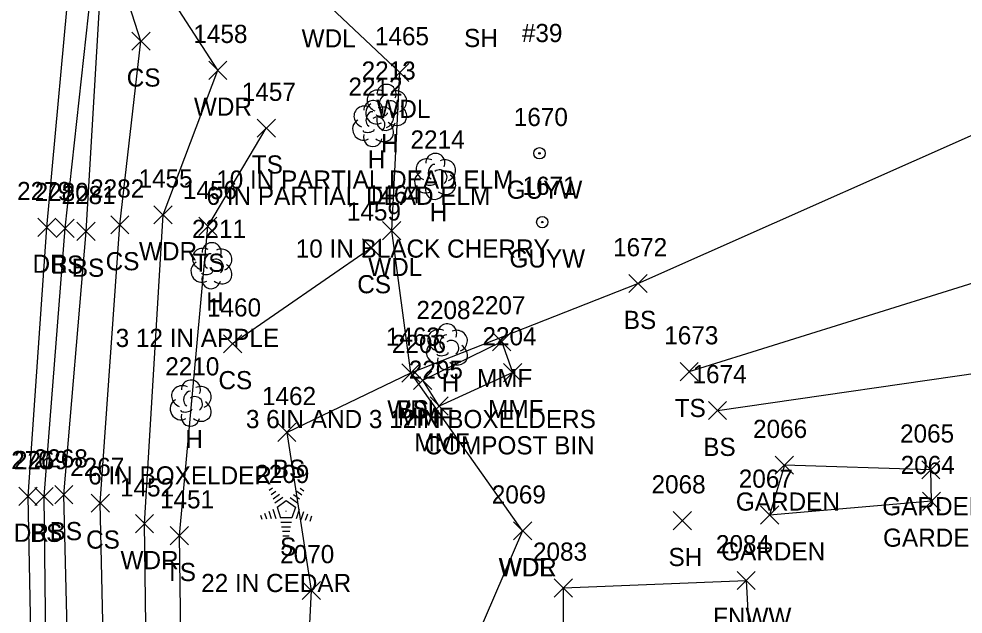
# Model space of a CAD drawing. Extents: x 1761340 to 1763889, y 696770 to 706023.
# Drawn here: x 1761657.7 to 1761761.6, y 700749.1 to 700814.6 of the extents above; entities that cross this region are included whole.
import ezdxf

# ---------------------------------------------------------------- set-up
doc = ezdxf.new("R2010")
doc.units = 0
for name, color, linetype in [('L_A', 7, 'Continuous'), ('L_C', 7, 'Continuous'), ('L_I', 7, 'Continuous'), ('L_TIC', 7, 'Continuous'), ('LAPB', 7, 'Continuous'), ('LAWA', 7, 'Continuous'), ('LDEFAULT', 7, 'Continuous'), ('LELB', 7, 'Continuous'), ('LFNC', 7, 'Continuous'), ('LTC', 7, 'Continuous'), ('LTD', 7, 'Continuous'), ('R_A', 7, 'Continuous'), ('R_I', 7, 'Continuous'), ('R_TIC', 7, 'Continuous'), ('RDP', 7, 'Continuous'), ('U_A', 7, 'Continuous'), ('U_C', 7, 'Continuous'), ('U_I', 7, 'Continuous'), ('UPGW', 7, 'Continuous')]:
    doc.layers.add(name, color=color, linetype=linetype)

msp = doc.modelspace()

# ---------------------------------------------------------------- linework, layer by layer
at = {"layer": 'L_TIC'}
for points in [[(1761670.15, 700811.18), (1761672.15, 700813.18)], [(1761672.15, 700811.18), (1761670.15, 700813.18)], [(1761678.61, 700807.98), (1761680.61, 700809.98)], [(1761680.61, 700807.98), (1761678.61, 700809.98)], [(1761698.63, 700807.73), (1761700.63, 700809.73)], [(1761700.63, 700807.73), (1761698.63, 700809.73)], [(1761683.94, 700801.61), (1761685.94, 700803.61)], [(1761685.94, 700801.61), (1761683.94, 700803.61)], [(1761672.58, 700792.07), (1761674.58, 700794.07)], [(1761674.58, 700792.07), (1761672.58, 700794.07)], [(1761661.81, 700790.59), (1761663.81, 700792.59)], [(1761663.81, 700790.59), (1761661.81, 700792.59)], [(1761664.11, 700790.25), (1761666.11, 700792.25)], [(1761666.11, 700790.25), (1761664.11, 700792.25)], [(1761667.83, 700790.97), (1761669.83, 700792.97)], [(1761669.83, 700790.97), (1761667.83, 700792.97)], [(1761677.52, 700790.8), (1761679.52, 700792.8)], [(1761679.52, 700790.8), (1761677.52, 700792.8)], [(1761697.74, 700790.33), (1761699.74, 700792.33)], [(1761699.74, 700790.33), (1761697.74, 700792.33)], [(1761695.51, 700788.44), (1761697.51, 700790.44)], [(1761697.51, 700788.44), (1761695.51, 700790.44)], [(1761724.83, 700784.51), (1761726.83, 700786.51)], [(1761726.83, 700784.51), (1761724.83, 700786.51)], [(1761680.24, 700777.88), (1761682.24, 700779.88)], [(1761682.24, 700777.88), (1761680.24, 700779.88)], [(1761709.84, 700778.12), (1761711.84, 700780.12)], [(1761711.84, 700778.12), (1761709.84, 700780.12)], [(1761709.84, 700778.12), (1761711.84, 700780.12)], [(1761711.84, 700778.12), (1761709.84, 700780.12)], [(1761699.84, 700774.67), (1761701.84, 700776.67)], [(1761701.84, 700774.67), (1761699.84, 700776.67)], [(1761699.84, 700774.67), (1761701.84, 700776.67)], [(1761701.84, 700774.67), (1761699.84, 700776.67)], [(1761711.05, 700774.71), (1761713.05, 700776.71)], [(1761713.05, 700774.71), (1761711.05, 700776.71)], [(1761711.05, 700774.71), (1761713.05, 700776.71)], [(1761713.05, 700774.71), (1761711.05, 700776.71)], [(1761730.46, 700774.82), (1761732.46, 700776.82)], [(1761732.46, 700774.82), (1761730.46, 700776.82)], [(1761701.15, 700773.87), (1761703.15, 700775.87)], [(1761703.15, 700773.87), (1761701.15, 700775.87)], [(1761702.96, 700771.03), (1761704.96, 700773.03)], [(1761704.96, 700771.03), (1761702.96, 700773.03)], [(1761733.57, 700770.54), (1761735.57, 700772.54)], [(1761735.57, 700770.54), (1761733.57, 700772.54)], [(1761686.21, 700768.13), (1761688.21, 700770.13)], [(1761688.21, 700768.13), (1761686.21, 700770.13)], [(1761740.94, 700764.52), (1761742.94, 700766.52)], [(1761742.94, 700764.52), (1761740.94, 700766.52)], [(1761757.04, 700764.01), (1761759.04, 700766.01)], [(1761759.04, 700764.01), (1761757.04, 700766.01)], [(1761659.49, 700761.08), (1761661.49, 700763.08)], [(1761661.49, 700761.08), (1761659.49, 700763.08)], [(1761661.67, 700761.27), (1761663.67, 700763.27)], [(1761663.67, 700761.27), (1761661.67, 700763.27)], [(1761665.68, 700760.34), (1761667.68, 700762.34)], [(1761667.68, 700760.34), (1761665.68, 700762.34)], [(1761757.12, 700760.55), (1761759.12, 700762.55)], [(1761759.12, 700760.55), (1761757.12, 700762.55)], [(1761757.12, 700760.55), (1761759.12, 700762.55)], [(1761759.12, 700760.55), (1761757.12, 700762.55)], [(1761739.31, 700759.04), (1761741.31, 700761.04)], [(1761741.31, 700759.04), (1761739.31, 700761.04)], [(1761739.31, 700759.04), (1761741.31, 700761.04)], [(1761741.31, 700759.04), (1761739.31, 700761.04)], [(1761670.55, 700758.08), (1761672.55, 700760.08)], [(1761672.55, 700758.08), (1761670.55, 700760.08)], [(1761729.7, 700758.42), (1761731.7, 700760.42)], [(1761731.7, 700758.42), (1761729.7, 700760.42)], [(1761712.14, 700757.3), (1761714.14, 700759.3)], [(1761714.14, 700757.3), (1761712.14, 700759.3)], [(1761712.14, 700757.3), (1761714.14, 700759.3)], [(1761714.14, 700757.3), (1761712.14, 700759.3)], [(1761674.38, 700756.77), (1761676.38, 700758.77)], [(1761676.38, 700756.77), (1761674.38, 700758.77)], [(1761736.74, 700751.83), (1761738.74, 700753.83)], [(1761738.74, 700751.83), (1761736.74, 700753.83)], [(1761688.89, 700750.74), (1761690.89, 700752.74)], [(1761690.89, 700750.74), (1761688.89, 700752.74)], [(1761716.62, 700751.01), (1761718.62, 700753.01)], [(1761718.62, 700751.01), (1761716.62, 700753.01)]]:
    msp.add_lwpolyline(points, dxfattribs=at)
at = {"layer": 'LAPB'}
for points in [[(1761758.12, 700761.55), (1761758.04, 700765.01), (1761741.94, 700765.52), (1761740.31, 700760.04)], [(1761758.12, 700761.55), (1761740.31, 700760.04)]]:
    msp.add_lwpolyline(points, dxfattribs=at)
at = {"layer": 'LAWA'}
for points in [[(1761700.84, 700775.67), (1761698.74, 700791.33), (1761699.63, 700808.73), (1761691.41, 700816.49), (1761688.6, 700828.09), (1761671.02, 700822.27)], [(1761671.88, 700734.04), (1761671.55, 700759.08), (1761673.58, 700793.07), (1761679.61, 700808.98), (1761671.02, 700822.27)], [(1761713.14, 700758.3), (1761700.84, 700775.67)], [(1761713.14, 700758.3), (1761701.74, 700731.81), (1761691.69, 700708.02), (1761692.15, 700678.39), (1761694.37, 700650.47), (1761696.35, 700624.4)]]:
    msp.add_lwpolyline(points, dxfattribs=at)
at = {"layer": 'LDEFAULT'}
for points in [[(1761712.05, 700775.71), (1761703.96, 700772.03), (1761702.15, 700774.87), (1761710.84, 700779.12)], [(1761712.05, 700775.71), (1761710.84, 700779.12)]]:
    msp.add_lwpolyline(points, dxfattribs=at)
at = {"layer": 'LELB'}
for points in [[(1761681.3, 700585.52), (1761671.93, 700613.51), (1761667.59, 700648.27), (1761662.96, 700684.4), (1761660.97, 700720.86), (1761660.49, 700762.08), (1761662.81, 700791.59), (1761666.16, 700822.15), (1761669.09, 700835.75), (1761669.55, 700847.22), (1761671.38, 700859.7), (1761679.65, 700896.38), (1761688.23, 700933.04), (1761696.4, 700960.96), (1761706.35, 700997.91), (1761723.36, 701026.16)], [(1761684.45, 700586.47), (1761674.15, 700613.84), (1761669.56, 700648.24), (1761665.94, 700684.58), (1761663.69, 700720.73), (1761662.67, 700762.27), (1761665.11, 700791.25), (1761666.95, 700822.18), (1761669.97, 700835.61), (1761670.38, 700847.09), (1761671.95, 700859.51), (1761680.67, 700895.81), (1761689.74, 700932.61), (1761697.72, 700961.08), (1761707.94, 700997.33), (1761724.65, 701022.11)], [(1761685.1, 700588.24), (1761679.12, 700609.9), (1761673.29, 700649.1), (1761669.6, 700684.44), (1761667.58, 700720.71), (1761666.68, 700761.34), (1761668.83, 700791.97), (1761671.15, 700812.18), (1761668.52, 700820.34)], [(1761687.21, 700769.13), (1761700.84, 700775.67), (1761725.83, 700785.51), (1761771.25, 700805.69), (1761793.07, 700814.61), (1761809.19, 700820.93)], [(1761675.74, 700733.1), (1761675.38, 700757.77), (1761678.52, 700791.8), (1761684.94, 700802.61)], [(1761731.46, 700775.82), (1761780.78, 700791.23), (1761787.31, 700781.1)], [(1761696.51, 700789.44), (1761681.24, 700778.88)], [(1761734.57, 700771.54), (1761766.51, 700776.17), (1761775.94, 700769.45)], [(1761687.21, 700769.13), (1761689.89, 700751.74)], [(1761689.89, 700751.74), (1761689.12, 700736.42), (1761691.69, 700708.02)]]:
    msp.add_lwpolyline(points, dxfattribs=at)
at = {"layer": 'LFNC'}
msp.add_lwpolyline([(1761718.72, 700664.11), (1761717.35, 700686.21), (1761717.32, 700714.11), (1761717.65, 700737.51), (1761717.62, 700752.01), (1761737.74, 700752.83), (1761739.58, 700719.28), (1761740.48, 700687), (1761739.09, 700665.05)], dxfattribs=at)
at = {"layer": 'LTC'}
for p, q in [((1761685.27, 700762.77), (1761685.63, 700763.02)), ((1761688.67, 700763.01), (1761689.09, 700762.7)), ((1761685.48, 700762.3), (1761686.01, 700762.68)), ((1761685.69, 700761.83), (1761686.4, 700762.35)), ((1761685.9, 700761.37), (1761686.78, 700762.01)), ((1761687.56, 700761.96), (1761688.37, 700761.37)), ((1761687.93, 700762.31), (1761688.61, 700761.82)), ((1761688.3, 700762.66), (1761688.85, 700762.26)), ((1761686.13, 700760.91), (1761687.14, 700761.65)), ((1761686.13, 700760.91), (1761686.51, 700759.72)), ((1761687.14, 700761.65), (1761688.14, 700760.92)), ((1761688.14, 700760.92), (1761687.74, 700759.72)), ((1761684.31, 700760.04), (1761684.46, 700759.58)), ((1761684.76, 700760.26), (1761684.97, 700759.61)), ((1761685.22, 700760.48), (1761685.49, 700759.64)), ((1761685.67, 700760.69), (1761686, 700759.67)), ((1761688.57, 700760.65), (1761688.24, 700759.61)), ((1761689.02, 700760.4), (1761688.73, 700759.52)), ((1761689.46, 700760.15), (1761689.23, 700759.42)), ((1761689.91, 700759.9), (1761689.72, 700759.33)), ((1761687.74, 700759.72), (1761686.51, 700759.72)), ((1761687.71, 700759.22), (1761686.56, 700759.22)), ((1761687.62, 700758.72), (1761686.63, 700758.72)), ((1761687.54, 700758.22), (1761686.71, 700758.22)), ((1761687.46, 700757.72), (1761686.78, 700757.72))]:
    msp.add_line(p, q, dxfattribs=at)
at = {"layer": 'LTD'}
for p, q in [((1761698.12, 700804.95), (1761698.12, 700804.95)), ((1761698.12, 700804.95), (1761698.12, 700804.95)), ((1761696.67, 700803.17), (1761696.67, 700803.17)), ((1761696.67, 700803.17), (1761696.67, 700803.17)), ((1761703.5, 700797.36), (1761703.5, 700797.36)), ((1761703.5, 700797.36), (1761703.5, 700797.36)), ((1761678.89, 700787.53), (1761678.89, 700787.53)), ((1761678.89, 700787.53), (1761678.89, 700787.53)), ((1761704.8, 700778.6), (1761704.8, 700778.6)), ((1761704.8, 700778.6), (1761704.8, 700778.6)), ((1761676.6, 700772.4), (1761676.6, 700772.4)), ((1761676.6, 700772.4), (1761676.6, 700772.4))]:
    msp.add_line(p, q, dxfattribs=at)
for centre in [(1761698.17, 700806.38), (1761696.72, 700804.6), (1761703.54, 700798.79), (1761678.94, 700788.96), (1761704.84, 700780.03), (1761676.65, 700773.84)]:
    msp.add_arc(centre, 1.05, 335.5272, 180.9563, dxfattribs=at)
for centre, major_axis, ratio, start_param, end_param in [((1761697.33, 700805.61), (1.21, -0.51), 0.895232, 1.570796, 4.712389), ((1761699.16, 700805.53), (-1.14, -0.48), 0.949671, 1.570796, 4.712389), ((1761697.91, 700805.41), (-0.208, -0.792), 0.645439, 3.141593, 6.283185), ((1761698.62, 700804.78), (-0.5, 0.667), 0.989748, 3.141593, 6.283185), ((1761695.88, 700803.84), (1.21, -0.51), 0.895232, 1.570796, 4.712389), ((1761697.04, 700804.24), (0.58, -1.04), 0.959034, 3.141593, 6.283185), ((1761696.46, 700803.63), (-0.208, -0.792), 0.645439, 3.141593, 6.283185), ((1761697.71, 700803.75), (-1.14, -0.48), 0.949671, 1.570796, 4.712389), ((1761699.12, 700804.11), (-1.09, 0.79), 0.841452, 1.570796, 4.712389), ((1761695.59, 700802.46), (0.58, -1.04), 0.959034, 3.141593, 6.283185), ((1761697.17, 700803), (-0.5, 0.667), 0.989748, 3.141593, 6.283185), ((1761698.12, 700803.45), (0.26, 1.06), 0.942809, 1.570796, 4.712389), ((1761697.66, 700804.2), (-0.625, -0.083), 0.423636, 0, 3.141593), ((1761696.21, 700802.42), (-0.625, -0.083), 0.423636, 0, 3.141593), ((1761697.67, 700802.34), (-1.09, 0.79), 0.841452, 1.570796, 4.712389), ((1761696.67, 700801.67), (0.26, 1.06), 0.942809, 1.570796, 4.712389), ((1761702.71, 700798.03), (1.21, -0.51), 0.895232, 1.570796, 4.712389), ((1761704.54, 700797.94), (-1.14, -0.48), 0.949671, 1.570796, 4.712389), ((1761703.29, 700797.82), (-0.208, -0.792), 0.645439, 3.141593, 6.283185), ((1761702.41, 700796.65), (0.58, -1.04), 0.959034, 3.141593, 6.283185), ((1761704, 700797.19), (-0.5, 0.667), 0.989748, 3.141593, 6.283185), ((1761704.5, 700796.53), (-1.09, 0.79), 0.841452, 1.570796, 4.712389), ((1761703.04, 700796.61), (-0.625, -0.083), 0.423636, 0, 3.141593), ((1761703.5, 700795.86), (0.26, 1.06), 0.942809, 1.570796, 4.712389), ((1761678.1, 700788.19), (1.21, -0.51), 0.895232, 1.570796, 4.712389), ((1761679.93, 700788.11), (-1.14, -0.48), 0.949671, 1.570796, 4.712389), ((1761677.81, 700786.82), (0.58, -1.04), 0.959034, 3.141593, 6.283185), ((1761678.68, 700787.99), (-0.208, -0.792), 0.645439, 3.141593, 6.283185), ((1761679.39, 700787.36), (-0.5, 0.667), 0.989748, 3.141593, 6.283185), ((1761678.43, 700786.78), (-0.625, -0.083), 0.423636, 0, 3.141593), ((1761679.89, 700786.69), (-1.09, 0.79), 0.841452, 1.570796, 4.712389), ((1761678.89, 700786.03), (0.26, 1.06), 0.942809, 1.570796, 4.712389), ((1761704, 700779.26), (1.21, -0.51), 0.895232, 1.570796, 4.712389), ((1761704.59, 700779.06), (-0.208, -0.792), 0.645439, 3.141593, 6.283185), ((1761705.84, 700779.18), (-1.14, -0.48), 0.949671, 1.570796, 4.712389), ((1761703.71, 700777.89), (0.58, -1.04), 0.959034, 3.141593, 6.283185), ((1761705.3, 700778.43), (-0.5, 0.667), 0.989748, 3.141593, 6.283185), ((1761705.8, 700777.77), (-1.09, 0.79), 0.841452, 1.570796, 4.712389), ((1761704.34, 700777.85), (-0.625, -0.083), 0.423636, 0, 3.141593), ((1761704.8, 700777.1), (0.26, 1.06), 0.942809, 1.570796, 4.712389), ((1761675.81, 700773.07), (1.21, -0.51), 0.895232, 1.570796, 4.712389), ((1761676.4, 700772.86), (-0.208, -0.792), 0.645439, 3.141593, 6.283185), ((1761677.65, 700772.99), (-1.14, -0.48), 0.949671, 1.570796, 4.712389), ((1761675.52, 700771.69), (0.58, -1.04), 0.959034, 3.141593, 6.283185), ((1761677.1, 700772.24), (-0.5, 0.667), 0.989748, 3.141593, 6.283185), ((1761677.6, 700771.57), (-1.09, 0.79), 0.841452, 1.570796, 4.712389), ((1761676.15, 700771.65), (-0.625, -0.083), 0.423636, 0, 3.141593), ((1761676.6, 700770.9), (0.26, 1.06), 0.942809, 1.570796, 4.712389)]:
    msp.add_ellipse(centre, major_axis=major_axis, ratio=ratio, start_param=start_param, end_param=end_param, dxfattribs=at)
at = {"layer": 'R_TIC'}
for points in [[(1761659.8, 700790.69), (1761661.8, 700792.69)], [(1761661.8, 700790.69), (1761659.8, 700792.69)], [(1761657.73, 700761.09), (1761659.73, 700763.09)], [(1761659.73, 700761.09), (1761657.73, 700763.09)]]:
    msp.add_lwpolyline(points, dxfattribs=at)
at = {"layer": 'RDP'}
msp.add_lwpolyline([(1761685.9, 700541.84), (1761678.4, 700578.09), (1761669.59, 700613.17), (1761665.81, 700647.63), (1761660.31, 700684.32), (1761659.55, 700721.03), (1761658.73, 700762.09), (1761660.8, 700791.69), (1761663.62, 700822.45), (1761666.15, 700836.34), (1761667.52, 700847.08), (1761668.95, 700859.68), (1761676.88, 700896.8), (1761686.16, 700933.2), (1761693.93, 700961.97), (1761704.59, 700998.32), (1761705.06, 700999.04), (1761715.84, 701034.88), (1761727.08, 701077.74), (1761742.29, 701129.68)], dxfattribs=at)
at = {"layer": 'UPGW'}
for centre, radius in [((1761715, 700799.84), 0.625), ((1761715, 700799.84), 0.0833), ((1761715.3, 700792.27), 0.625), ((1761715.3, 700792.27), 0.0833)]:
    msp.add_circle(centre, radius, dxfattribs=at)

# ---------------------------------------------------------------- texts
at = {"layer": 'L_A'}
for s, p in [('WDL', (1761688.83, 700811.49)), ('SH', (1761706.7, 700811.53)), ('CS', (1761669.59, 700807.18)), ('WDR', (1761676.98, 700803.98)), ('WDL', (1761697.05, 700803.73)), ('H', (1761697.56, 700799.95)), ('TS', (1761683.35, 700797.61)), ('H', (1761696.1, 700798.17)), ('H', (1761702.93, 700792.36)), ('WDR', (1761670.94, 700788.07)), ('CS', (1761667.27, 700786.97)), ('BS', (1761661.25, 700786.59)), ('BS', (1761663.55, 700786.25)), ('TS', (1761676.93, 700786.8)), ('WDL', (1761696.16, 700786.33)), ('CS', (1761694.95, 700784.44)), ('H', (1761678.33, 700782.53)), ('BS', (1761724.27, 700780.51)), ('CS', (1761679.68, 700773.88)), ('H', (1761704.23, 700773.6)), ('MMF', (1761708.12, 700774.12)), ('MMF', (1761708.12, 700774.12)), ('WDL', (1761698.25, 700770.67)), ('BS', (1761699.28, 700770.67)), ('MMF', (1761709.34, 700770.71)), ('MMF', (1761709.34, 700770.71)), ('TS', (1761729.87, 700770.82)), ('MMF', (1761699.43, 700769.87)), ('H', (1761676.04, 700767.4)), ('MMF', (1761701.24, 700767.03)), ('BS', (1761733.01, 700766.54)), ('BS', (1761685.65, 700764.13)), ('GARDEN', (1761736.6, 700760.52)), ('GARDEN', (1761752.71, 700760.01)), ('BS', (1761658.94, 700757.08)), ('BS', (1761661.11, 700757.27)), ('CS', (1761665.12, 700756.34)), ('GARDEN', (1761752.79, 700756.55)), ('GARDEN', (1761752.79, 700756.55)), ('S', (1761686.46, 700755.56)), ('GARDEN', (1761734.98, 700755.04)), ('GARDEN', (1761734.98, 700755.04)), ('WDR', (1761668.91, 700754.08)), ('SH', (1761729.19, 700754.42)), ('TS', (1761673.79, 700752.77)), ('WDR', (1761710.5, 700753.3)), ('WDL', (1761710.56, 700753.3)), ('FNWW', (1761734.09, 700747.83))]:
    msp.add_text(s, height=2, dxfattribs=at).set_placement(p)
at = {"layer": 'L_C'}
for s, p in [('10 IN PARTIAL DEAD ELM', (1761679.43, 700795.95)), ('6 IN PARTIAL DEAD ELM', (1761678.37, 700794.17)), ('10 IN BLACK CHERRY', (1761688.18, 700788.36)), ('3 12 IN APPLE', (1761668.37, 700778.53)), ('3 6IN AND 3 12IN BOXELDERS', (1761682.7, 700769.6)), ('COMPOST BIN', (1761702.35, 700766.71)), ('COMPOST BIN', (1761702.35, 700766.71)), ('6 IN BOXELDER', (1761665.35, 700763.4)), ('22 IN CEDAR', (1761677.78, 700751.56))]:
    msp.add_text(s, height=2, dxfattribs=at).set_placement(p)
at = {"layer": 'L_I'}
for s, p in [('1458', (1761676.92, 700811.98)), ('1465', (1761696.89, 700811.73)), ('2213', (1761695.43, 700807.95)), ('1457', (1761682.25, 700805.61)), ('2212', (1761693.98, 700806.17)), ('2214', (1761700.81, 700800.36)), ('1455', (1761670.89, 700796.07)), ('2280', (1761659.46, 700794.59)), ('2281', (1761662.42, 700794.25)), ('2282', (1761665.57, 700794.97)), ('1456', (1761675.77, 700794.8)), ('1464', (1761696, 700794.33)), ('1459', (1761693.81, 700792.44)), ('2211', (1761676.77, 700790.53)), ('1672', (1761723.09, 700788.51)), ('1460', (1761678.42, 700781.88)), ('2207', (1761707.5, 700782.12)), ('2207', (1761707.5, 700782.12)), ('2208', (1761701.46, 700781.6)), ('1463', (1761698.1, 700778.67)), ('1463', (1761698.1, 700778.67)), ('2204', (1761708.72, 700778.71)), ('2204', (1761708.72, 700778.71)), ('1673', (1761728.72, 700778.82)), ('2206', (1761698.76, 700777.87)), ('2210', (1761673.83, 700775.4)), ('2205', (1761700.62, 700775.03)), ('1674', (1761731.83, 700774.54)), ('1462', (1761684.47, 700772.13)), ('2066', (1761738.49, 700768.52)), ('2065', (1761754.66, 700768.01)), ('2269', (1761657.18, 700765.08)), ('2268', (1761659.36, 700765.27)), ('2267', (1761663.37, 700764.34)), ('2064', (1761754.73, 700764.55)), ('2064', (1761754.73, 700764.55)), ('2209', (1761683.73, 700763.56)), ('2067', (1761736.92, 700763.04)), ('2067', (1761736.92, 700763.04)), ('1452', (1761668.85, 700762.08)), ('2068', (1761727.32, 700762.42)), ('2069', (1761709.75, 700761.3)), ('2069', (1761709.75, 700761.3)), ('1451', (1761673.25, 700760.77)), ('2084', (1761734.4, 700755.83)), ('2070', (1761686.47, 700754.74)), ('2083', (1761714.28, 700755.01))]:
    msp.add_text(s, height=2, dxfattribs=at).set_placement(p)
at = {"layer": 'LTC'}
msp.add_text('.', height=1.04, rotation=270, dxfattribs=at).set_placement((1761687.02, 700760.66))
at = {"layer": 'R_A'}
for p in [(1761659.23, 700786.69), (1761657.17, 700757.09)]:
    msp.add_text('DR', height=2, dxfattribs=at).set_placement(p)
at = {"layer": 'R_I'}
for s, p in [('2279', (1761657.53, 700794.69)), ('2270', (1761655.39, 700765.09))]:
    msp.add_text(s, height=2, dxfattribs=at).set_placement(p)
at = {"layer": 'U_A'}
for p in [(1761711.39, 700794.84), (1761711.69, 700787.27)]:
    msp.add_text('GUYW', height=2, dxfattribs=at).set_placement(p)
at = {"layer": 'U_C'}
msp.add_text('#39', height=2, dxfattribs=at).set_placement((1761713.06, 700812.08))
at = {"layer": 'U_I'}
for s, p in [('1670', (1761712.17, 700802.84)), ('1671', (1761713.13, 700795.27))]:
    msp.add_text(s, height=2, dxfattribs=at).set_placement(p)

doc.saveas('drawing.dxf')
